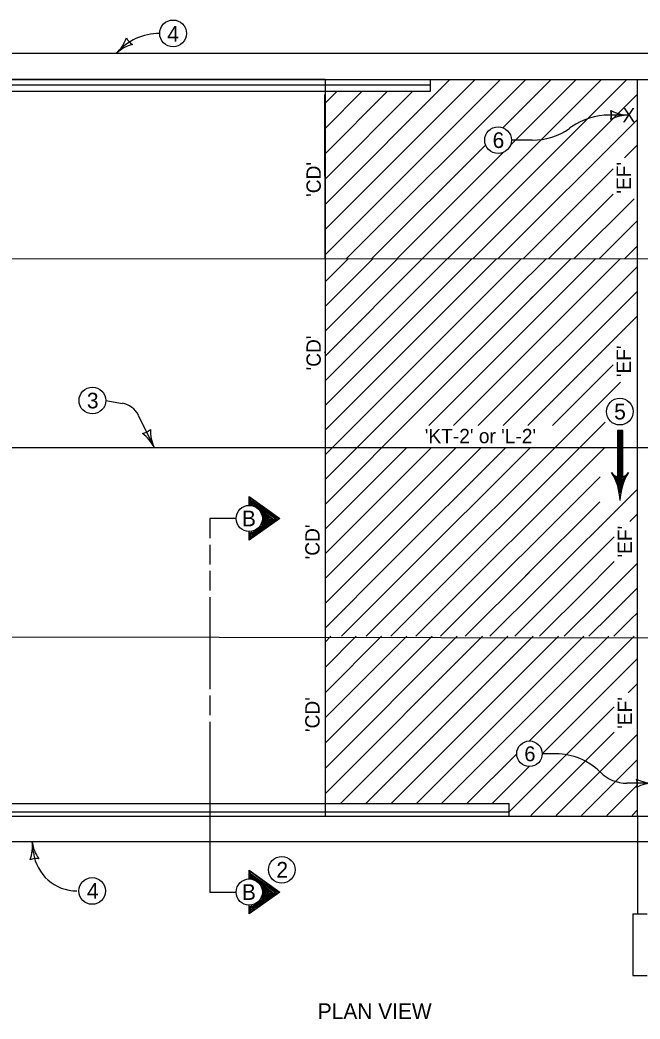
# Model space of a CAD drawing. Extents: x 9234 to 81668, y 5635 to 15999.
# Drawn here: x 21381 to 22109, y 5635 to 6810 of the extents above; entities that cross this region are included whole.
import ezdxf

# ---------------------------------------------------------------- set-up
doc = ezdxf.new("R2010")
doc.units = 0
doc.layers.add('PS_BOLT', color=7, linetype='Continuous')
doc.layers.add('PS_DIM', color=7, linetype='Continuous')

msp = doc.modelspace()

# ---------------------------------------------------------------- linework, layer by layer
msp.add_line((21369.1, 6739.7), (22915.9, 6739.7))
at = {"layer": 'PS_BOLT'}
for p, q in [((21481.6, 6362.3), (21501.2, 6359)), ((21519.9, 6345.1), (21538.6, 6307.2)), ((22098.9, 6105.6), (22106.2, 6112.9)), ((20929.9, 6085.2), (22915.9, 6081.9)), ((21604, 5984.7), (21604, 5784.5)), ((22010.6, 5947.1), (21994.4, 5947.1)), ((22125.2, 5912.4), (22093.9, 5912.4)), ((21396.9, 5830.8), (21395.2, 5843.8))]:
    msp.add_line(p, q, dxfattribs=at)
for points in [[(21634.8, 6223.7), (21604, 6223.7), (21604, 6200.5)], [(21604, 6192.8), (21604, 6169.7)], [(21604, 6162), (21604, 6138.9)], [(21604, 6131.2), (21604, 6023.2)], [(21604, 6015.5), (21604, 5992.4)], [(21604, 5795.9), (21604, 5784.5), (21634.8, 5784.5)]]:
    msp.add_lwpolyline(points, dxfattribs=at)
for centre, radius, start, end in [((21544.9, 6727.1), 66.8, 90, 139.4393), ((21496.9, 6333.7), 25.7, 26.2458, 80.4677), ((22010.6, 5873.6), 73.4, 45, 90), ((22093.9, 5956.5), 44.1, 225, 270), ((21447.8, 5837.2), 51.4, 187.2287, 270)]:
    msp.add_arc(centre, radius, start, end, dxfattribs=at)
at = {"layer": 'PS_DIM'}
for p, q in [((20993.3, 6770.5), (22915.9, 6770.5)), ((21078.8, 6739.7), (21645.4, 6739.7)), ((21078.8, 6733.5), (21863.2, 6733.5)), ((21369.1, 6739.7), (21739.2, 6739.7)), ((21739.2, 6739.7), (21369.1, 6739.7)), ((21739.2, 6739.7), (21739.2, 6085.2)), ((21739.2, 6533.5), (21945.3, 6739.7)), ((21739.2, 6563.2), (21915.6, 6739.7)), ((21739.2, 6592.9), (21885.9, 6739.7)), ((21764.6, 6529.2), (21975, 6739.7)), ((21853.7, 6529.2), (22064.1, 6739.7)), ((21863.2, 6725.8), (21863.2, 6739.7)), ((21883.4, 6529.2), (22093.8, 6739.7)), ((21948, 6683), (22004.7, 6739.7)), ((21956.7, 6662), (22034.4, 6739.7)), ((22106.2, 6529.2), (22106.2, 6739.7)), ((20965.7, 6725.8), (21863.2, 6725.8)), ((21739.2, 6529.2), (21739.1, 6722)), ((21739.2, 6622.6), (21842.4, 6725.8)), ((21739.2, 6652.3), (21812.7, 6725.8)), ((21739.2, 6682), (21783, 6725.8)), ((21739.2, 6711.7), (21753.3, 6725.8)), ((21913.1, 6529.2), (22106.2, 6722.3)), ((22106.2, 6529.2), (22106.2, 6714.3)), ((22095.9, 6697.9), (22073.1, 6697.9)), ((21942.8, 6529.2), (22106.2, 6692.6)), ((22028.9, 6684), (22026.6, 6682.4)), ((21794.3, 6529.2), (21928, 6662.9)), ((21982.4, 6668.4), (21958.2, 6668.4)), ((22091, 6647.7), (22106.2, 6662.9)), ((21824, 6529.2), (21949.3, 6654.5)), ((21972.5, 6529.2), (22077.7, 6634.5)), ((22002.2, 6529.2), (22077.7, 6604.8)), ((22031.9, 6529.2), (22102.2, 6599.6)), ((22061.6, 6529.2), (22106.2, 6573.8)), ((22091.3, 6529.2), (22106.2, 6544.1)), ((22915.9, 6528.2), (20883.2, 6529.2)), ((21739.2, 6501.9), (21766.6, 6529.2)), ((21739.2, 6472.8), (21795.6, 6529.2)), ((21739.2, 6443.7), (21824.7, 6529.2)), ((21739.2, 6414.6), (21853.8, 6529.2)), ((21739.2, 6385.6), (21882.9, 6529.2)), ((21739.2, 6356.5), (21911.9, 6529.2)), ((21739.2, 6327.4), (21941, 6529.2)), ((21890.2, 6333), (22077.9, 6520.7)), ((21919.3, 6333), (22106.2, 6519.9)), ((21943.8, 6503), (21970.1, 6529.2)), ((21961.2, 6491.3), (21999.2, 6529.2)), ((21987.2, 6488.2), (22028.2, 6529.2)), ((22035.5, 6507.5), (22057.3, 6529.2)), ((22077.9, 6520.7), (22086.4, 6529.2)), ((22106.2, 6085.2), (22106.2, 6529.2)), ((21861.1, 6333), (22035.5, 6507.5)), ((21739.2, 6298.3), (21943.8, 6503)), ((21739.2, 6269.3), (21961.2, 6491.3)), ((21852.7, 6353.7), (21987.2, 6488.2)), ((21948.3, 6333), (22106.2, 6490.9)), ((21987.2, 6488.2), (21980.3, 6481.3)), ((21977.4, 6333), (22106.2, 6461.8)), ((21738.7, 6419.3), (21739.2, 6419.7)), ((22006.5, 6333), (22077.7, 6404.3)), ((21787.7, 6085.2), (22086.4, 6383.9)), ((21739.2, 6240.2), (21852.7, 6353.7)), ((21816.7, 6085.2), (22068.4, 6336.8)), ((22085.8, 6272.5), (22085.8, 6327)), ((21369.1, 6307.2), (23250.3, 6307.2)), ((21739.2, 6211.1), (21835.3, 6307.2)), ((21739.2, 6182), (21864.3, 6307.2)), ((21739.2, 6153), (21893.4, 6307.2)), ((21739.2, 6123.9), (21922.5, 6307.2)), ((21813.5, 6169.1), (21951.6, 6307.2)), ((21828, 6154.6), (21980.6, 6307.2)), ((21845.8, 6085.2), (22067.9, 6307.2)), ((21874.9, 6085.2), (22062.4, 6272.7)), ((22082.7, 6272.6), (22082.7, 6272.6)), ((22089.1, 6272.7), (22089.1, 6272.7)), ((21991.3, 6143.4), (22106.2, 6258.3)), ((21974.9, 6156.1), (22062, 6243.2)), ((22097.1, 6220.1), (22106.2, 6229.2)), ((22019.8, 6142.9), (22079, 6202)), ((21739.2, 6094.8), (21813.5, 6169.1)), ((22042.3, 6136.3), (22079, 6173)), ((22058.8, 6123.6), (22106.2, 6171)), ((21758.6, 6085.2), (21828, 6154.6)), ((21904, 6085.2), (21979, 6160.2)), ((21933, 6085.2), (21991.3, 6143.4)), ((21962.1, 6085.2), (22019.8, 6142.9)), ((21991.2, 6085.2), (22046.7, 6140.7)), ((22074.3, 6110.1), (22106.2, 6142)), ((22020.3, 6085.2), (22061.9, 6126.8)), ((22049.3, 6085.2), (22074.3, 6110.1)), ((22078.4, 6085.2), (22098.9, 6105.6)), ((21739.2, 6085.2), (21739.2, 5900.1)), ((21739.2, 6085.2), (21739.2, 5874.7)), ((21739.2, 5900.1), (21924.3, 6085.2)), ((21739.2, 5929.8), (21894.6, 6085.2)), ((21739.2, 5959.5), (21864.9, 6085.2)), ((21739.2, 6018.9), (21805.5, 6085.2)), ((21739.2, 6048.6), (21775.8, 6085.2)), ((21739.2, 6078.3), (21746.1, 6085.2)), ((21739.2, 5989.2), (21835.2, 6085.2)), ((21757.4, 5888.6), (21954, 6085.2)), ((21787.1, 5888.6), (21983.7, 6085.2)), ((21816.8, 5888.6), (22013.4, 6085.2)), ((21846.5, 5888.6), (22043.1, 6085.2)), ((21876.2, 5888.6), (22072.8, 6085.2)), ((21979.4, 5962.1), (22102.5, 6085.2)), ((22106.2, 5874.7), (22106.2, 6085.2)), ((21994.2, 5947.2), (22106.2, 6059.2)), ((22095.3, 6018.6), (22106.2, 6029.5)), ((21955.7, 5879), (22079, 6002.3)), ((21981.1, 5874.7), (22079, 5972.6)), ((22010.8, 5874.7), (22106.2, 5970.1)), ((21905.9, 5888.6), (21964.6, 5947.2)), ((21935.6, 5888.6), (21979.4, 5932.4)), ((22040.5, 5874.7), (22106.2, 5940.4)), ((22070.2, 5874.7), (22106.2, 5910.7)), ((21049.8, 5888.6), (21955.7, 5888.6)), ((21955.7, 5873.9), (21955.7, 5888.6)), ((21068.7, 5879), (21955.7, 5879)), ((21078.8, 5873.9), (22915.9, 5873.9)), ((22099.9, 5874.7), (22106.2, 5881)), ((22106.2, 5874.7), (22106.2, 5759)), ((21078.8, 5843.8), (21406.1, 5843.8)), ((21406.1, 5843.8), (22915.9, 5843.8)), ((22101, 5759), (22117.5, 5759)), ((22101, 5759), (22101, 5686.6)), ((22101, 5686.6), (22117.5, 5686.6))]:
    msp.add_line(p, q, dxfattribs=at)
for points in [[(22106.2, 6529.2), (22106.2, 6529.2)], [(22088.9, 6272.6), (22088.9, 6327), (22082.7, 6327), (22082.7, 6272.6), (22088, 6272.8), (22088.2, 6326.3), (22083.3, 6326.2), (22083.5, 6273.8), (22087.1, 6273.7), (22087.3, 6325.6), (22084.1, 6325.5), (22084.1, 6274.5), (22086.4, 6274.4), (22086.7, 6325), (22084.8, 6324.9), (22084.9, 6275.2)], [(22092.9, 6274.1), (22089.2, 6271.8), (22083.8, 6271.5), (22079.1, 6273.5), (22082.4, 6265.4), (22085.2, 6256), (22085.8, 6253.4), (22087.1, 6260.2), (22090.6, 6270.1), (22092.1, 6273), (22080.7, 6271.9), (22085.6, 6257.4), (22089.9, 6271.6), (22082, 6271), (22085.6, 6261.1), (22087.9, 6270.2), (22083.3, 6270.6), (22085.4, 6264.3), (22086.7, 6269.1), (22084.6, 6269.4), (22085.2, 6267.1)], [(21650.2, 6239.1), (21650.2, 6249.4), (21686.2, 6223.7), (21650.2, 6198), (21650.2, 6208.3)], [(21651.2, 6207.2), (21651.2, 6199.8), (21684.3, 6223.7), (21651.1, 6247.7), (21651.3, 6239.8), (21652.7, 6239.4), (21652.2, 6245.2), (21682.1, 6223.7), (21652.2, 6201.9), (21652.5, 6207.4), (21653.6, 6207.6), (21653.5, 6204), (21680.1, 6223.8), (21653.4, 6242.5), (21654, 6239.4), (21655.1, 6239), (21655, 6240.1), (21677.8, 6223.4), (21654.6, 6205.9), (21655.7, 6207.9), (21675.8, 6223.3), (21663.5, 6233.1), (21664.3, 6231.3), (21673.7, 6223.2), (21664.6, 6216.2), (21665.4, 6218.1), (21671.8, 6223), (21665.4, 6228.5), (21666.1, 6226.1), (21670.2, 6222.9), (21666, 6219.7), (21666.2, 6221.4), (21668.6, 6222.8), (21666.3, 6224.2), (21666.4, 6222.8), (21667.2, 6222.8)], [(22106.2, 6085.2), (22106.2, 6085.2)], [(21650.2, 5799.9), (21650.2, 5810.2), (21686.2, 5784.5), (21650.2, 5758.8), (21650.2, 5769)], [(21651.2, 5768), (21651.2, 5760.6), (21684.3, 5784.5), (21651.1, 5808.5), (21651.3, 5800.6), (21652.7, 5800.2), (21652.2, 5806), (21682.1, 5784.5), (21652.2, 5762.7), (21652.5, 5768.2), (21653.6, 5768.4), (21653.5, 5764.8), (21680.1, 5784.5), (21653.4, 5803.3), (21654, 5800.1), (21655.1, 5799.8), (21655, 5800.9), (21677.8, 5784.2), (21654.6, 5766.7), (21655.7, 5768.6), (21675.8, 5784.1), (21663.5, 5793.9), (21664.3, 5792.1), (21673.7, 5784), (21664.6, 5777), (21665.4, 5778.9), (21671.8, 5783.8), (21665.4, 5789.3), (21666.1, 5786.9), (21670.2, 5783.7), (21666, 5780.4), (21666.2, 5782.1), (21668.6, 5783.6), (21666.3, 5785), (21666.4, 5783.5), (21667.2, 5783.6)]]:
    msp.add_lwpolyline(points, dxfattribs=at)
for centre, radius in [((21560.7, 6793.9), 15.7), ((21942.5, 6668.4), 15.7), ((21465.9, 6362.3), 15.7), ((22085.5, 6349.3), 15.7), ((21650.2, 6223.7), 15.4), ((21979.4, 5947.1), 15), ((21688.4, 5810.7), 15.7), ((21465.7, 5785.8), 15.7), ((21650.2, 5784.5), 15.4)]:
    msp.add_circle(centre, radius, dxfattribs=at)
for centre, radius, start, end in [((21464, 6803.1), 44.4, 312.7719, 340.8444), ((21521.5, 6795.8), 17.1, 205.0386, 240.5053), ((21524.3, 6737.9), 44.4, 104.6994, 132.7719), ((22073.1, 6620.8), 77.1, 90, 124.9993), ((22058.6, 6697.9), 17.1, 342.2666, 17.7334), ((22095.9, 6742.3), 44.4, 241.9275, 270), ((22058.7, 6697.9), 17.1, 342.2666, 17.7334), ((22095.9, 6742.3), 44.4, 241.9275, 270), ((22095.9, 6653.5), 44.4, 90, 118.0725), ((22095.9, 6653.5), 44.4, 90, 118.0725), ((21982.4, 6745.5), 77.1, 270, 304.9999), ((21522.2, 6340.6), 17.1, 278.5122, 313.9789), ((21498.8, 6287.6), 44.4, 26.2455, 54.318), ((21578.4, 6326.8), 44.4, 178.1731, 206.2455), ((22085.8, 6283.8), 11.6, 211.7147, 328.2853), ((22019.5, 6242.9), 66.3, 1.6842, 31.7143), ((22152, 6242.9), 66.3, 148.2857, 178.3158), ((22089.7, 5912.4), 16.3, 342.2666, 17.7333), ((22125.2, 5954.7), 42.3, 241.9275, 270), ((22125.2, 5870.2), 42.3, 90, 118.0725), ((21351.2, 5838.2), 44.4, 339.1562, 7.2287), ((21439.2, 5849.4), 44.4, 187.2287, 215.3012), ((21399.9, 5806.9), 17.1, 79.4954, 114.9621)]:
    msp.add_arc(centre, radius, start, end, dxfattribs=at)

# ---------------------------------------------------------------- texts
at = {"layer": 'PS_BOLT'}
for s, height, p in [('4', 18.4, (21553.9, 6784.1)), ('X', 16.8, (22088.7, 6689.5)), ('6', 18.4, (21936.1, 6659.2)), ('3', 18.4, (21459.5, 6353.1)), ('5', 18.4, (22078.9, 6340.1)), ("'KT-2' or 'L-2'", 16.8, (21856.4, 6312.2)), ('B', 18.4, (21641.6, 6214.5)), ('6', 17.5, (21973.4, 5938.3)), ('2', 18.4, (21682.1, 5801.5)), ('4', 18.4, (21459.6, 5776.6)), ('B', 18.4, (21641.6, 5775.3)), ('PLAN VIEW', 18.37, (21730.7, 5635.3))]:
    msp.add_text(s, height=height, dxfattribs=at).set_placement(p)
for s, p in [("'CD'", (21734.2, 6601.7)), ("'EF'", (22098.5, 6605.5)), ("'CD'", (21734.2, 6397.7)), ("'EF'", (22098.5, 6389.8)), ("'CD'", (21732.8, 6175.6)), ("'EF'", (22099.8, 6177.8)), ("'CD'", (21732.8, 5972.6)), ("'EF'", (22099.8, 5976.4))]:
    msp.add_text(s, height=16.8, rotation=90, dxfattribs=at).set_placement(p)

doc.saveas('drawing.dxf')
